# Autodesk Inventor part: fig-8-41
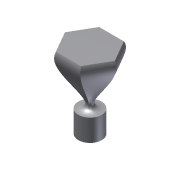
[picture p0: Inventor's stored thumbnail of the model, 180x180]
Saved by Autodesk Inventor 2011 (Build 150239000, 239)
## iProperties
Created: 2004-05
Part Number: fig-8-41
Document SubType Name: Modeling
Designer: CADCIM Technologies
Manufacturer: Standard
Standards Organization: Custom
Density: 1 g/cm^3
Author: CADCIM Technologies
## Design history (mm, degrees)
sketch "Sketch1"
  geometry: C1 r 16.344 at (0, 0)
  constraints: 1 centre point
extrude "Extrusion1" new body sketch "Sketch1" distance "d0" = 30.75; taper "d1" = 0 deg
workplane "Work Plane1"
sketch "Sketch2"
  geometry: L1 (34.788, 0)-(17.394, -30.128); L2 (17.394, -30.128)-(-17.394, -30.128); L3 (-17.394, -30.128)-(-34.788, 0); L4 (-34.788, 0)-(-17.394, 30.128); L5 (-17.394, 30.128)-(17.394, 30.128); L6 (17.394, 30.128)-(34.788, 0); 2 further points
  constraints: 12 end point, 1 coincident, 12 other
loft "Loft2" sketch "Sketch2" dims "d9" = 15, "d10" = 90 deg, "d11" = 80, "d12" = 120 deg
  node "Edges2"
body "Solid1"
other parameters: "d2" = 75
